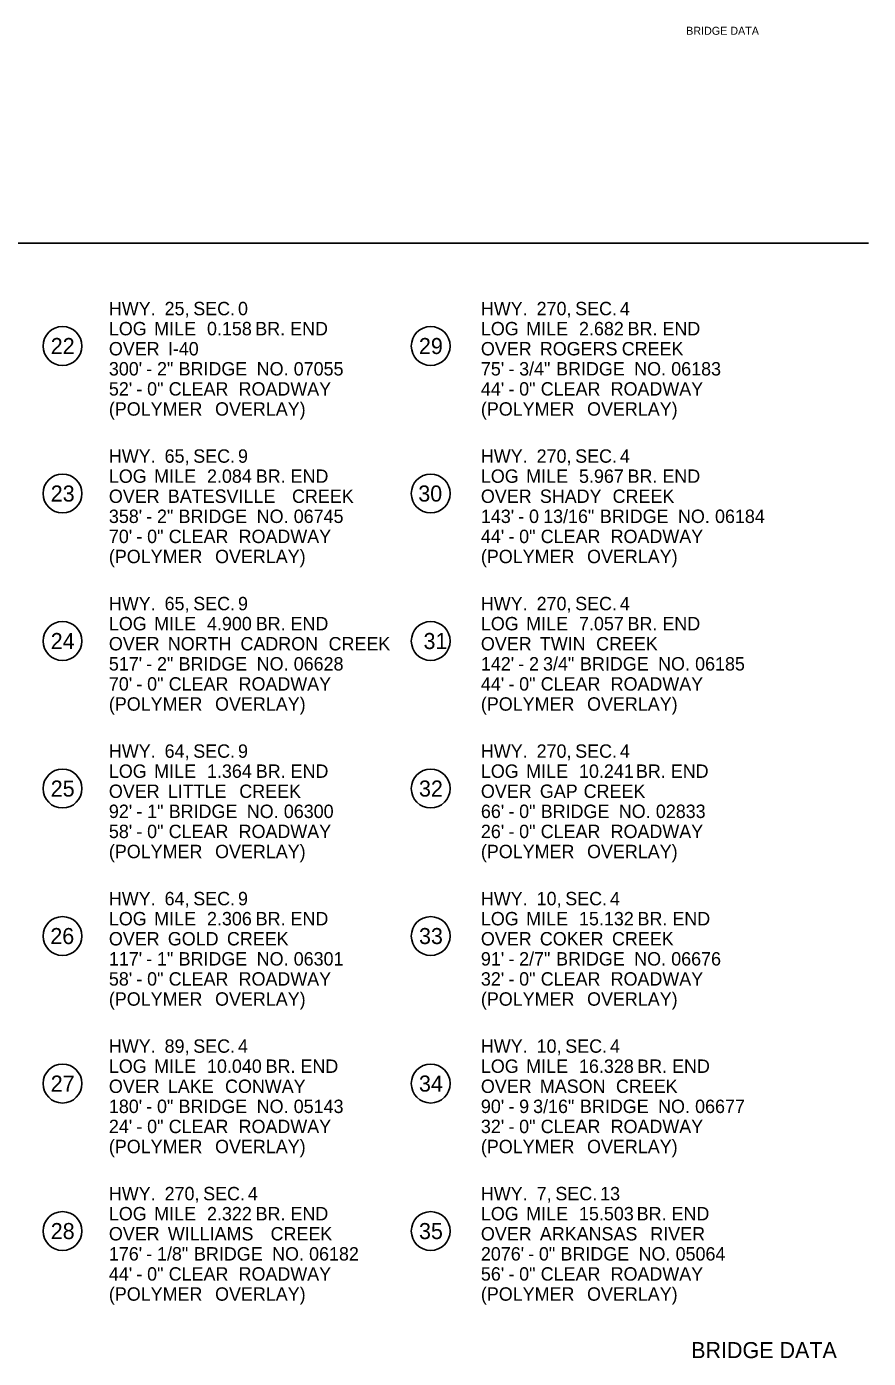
# Model space of a CAD drawing. Extents: x 1930546 to 1934225, y 596452 to 599553.
# Drawn here: x 1931513 to 1932142, y 598531 to 599525 of the extents above; entities that cross this region are included whole.
import ezdxf

# ---------------------------------------------------------------- set-up
doc = ezdxf.new("R2010")
doc.units = 0
for name, color, linetype in [('Default', 7, 'Continuous'), ('R_Border', 7, 'Continuous'), ('S_AREA_CALC', 7, 'Continuous')]:
    doc.layers.add(name, color=color, linetype=linetype)

msp = doc.modelspace()

# ---------------------------------------------------------------- linework, layer by layer
at = {"layer": 'R_Border'}
msp.add_line((1932141.6, 599363.54), (1930546.24, 599363.54), dxfattribs=at)
for centre in [(1931539.67, 599286.71), (1931814.72, 599286.71), (1931539.67, 599176.53), (1931814.72, 599176.53), (1931539.67, 599066.36), (1931814.72, 599066.36), (1931539.67, 598956.18), (1931814.72, 598956.18), (1931539.67, 598846.01), (1931814.72, 598846.01), (1931539.67, 598735.83), (1931814.72, 598735.83), (1931539.67, 598625.66), (1931814.72, 598625.66)]:
    msp.add_circle(centre, 14.52, dxfattribs=at)

# ---------------------------------------------------------------- texts
at = {"layer": 'Default'}
for s, p in [('HWY.', (1931574.31, 599309.69)), (' 25,', (1931612.22, 599309.69)), (' SEC.', (1931633.62, 599309.69)), (' 0', (1931667.03, 599309.69)), ('HWY.', (1931852.18, 599309.69)), (' 270,', (1931890.09, 599309.69)), (' SEC.', (1931918.89, 599309.69)), (' 4', (1931952.3, 599309.69)), ('LOG', (1931574.31, 599294.69)), (' MILE', (1931604.44, 599294.69)), (' 0.158', (1931643.88, 599294.69)), (' BR.', (1931679.96, 599294.69)), (' END', (1931706, 599294.69)), ('LOG', (1931852.18, 599294.69)), (' MILE', (1931882.31, 599294.69)), (' 2.682', (1931921.75, 599294.69)), (' BR.', (1931958.07, 599294.69)), (' END', (1931984.1, 599294.69)), ('OVER', (1931574.31, 599279.69)), (' I-40', (1931614.64, 599279.69)), ('OVER', (1931852.18, 599279.69)), (' ROGERS', (1931892.51, 599279.69)), (' CREEK', (1931953.68, 599279.69)), ("300'", (1931574.31, 599264.69)), (' 2"', (1931606.54, 599264.69)), (' BRIDGE', (1931622.67, 599264.69)), (' NO.', (1931680.99, 599264.69)), (' 07055', (1931708.65, 599264.69)), ("75'", (1931852.18, 599264.69)), (' 3/4"', (1931877.03, 599264.69)), (' BRIDGE', (1931904.65, 599264.69)), (' NO.', (1931962.97, 599264.69)), (' 06183', (1931990.63, 599264.69)), (' -', (1931598.51, 599264.69)), (' -', (1931869, 599264.69)), ("52'", (1931574.31, 599249.69)), (' -', (1931591.12, 599249.69)), (' 0"', (1931599.15, 599249.69)), (' CLEAR', (1931615.28, 599249.69)), (' ROADWAY', (1931667.5, 599249.69)), ("44'", (1931852.18, 599249.69)), (' -', (1931869, 599249.69)), (' 0"', (1931877.03, 599249.69)), (' CLEAR', (1931893.16, 599249.69)), (' ROADWAY', (1931945.38, 599249.69)), ('(POLYMER', (1931574.31, 599234.69)), (' OVERLAY)', (1931649.92, 599234.69)), ('(POLYMER', (1931852.18, 599234.69)), (' OVERLAY)', (1931927.79, 599234.69)), ('HWY.', (1931574.31, 599199.52)), (' 65,', (1931612.22, 599199.52)), (' SEC.', (1931633.62, 599199.52)), (' 9', (1931667.03, 599199.52)), ('HWY.', (1931852.18, 599199.52)), (' 270,', (1931890.09, 599199.52)), (' SEC.', (1931918.89, 599199.52)), (' 4', (1931952.3, 599199.52)), ('LOG', (1931574.31, 599184.52)), (' MILE', (1931604.44, 599184.52)), (' 2.084', (1931643.88, 599184.52)), (' BR.', (1931680.3, 599184.52)), (' END', (1931706.33, 599184.52)), ('LOG', (1931852.18, 599184.52)), (' MILE', (1931882.31, 599184.52)), (' 5.967', (1931921.75, 599184.52)), (' BR.', (1931958.02, 599184.52)), (' END', (1931984.05, 599184.52)), ('OVER', (1931574.31, 599169.52)), (' BATESVILLE', (1931614.64, 599169.52)), (' CREEK', (1931707.39, 599169.52)), ('OVER', (1931852.18, 599169.52)), (' SHADY', (1931892.51, 599169.52)), (' CREEK', (1931946.86, 599169.52)), ("358'", (1931574.31, 599154.52)), (' 2"', (1931606.54, 599154.52)), (' BRIDGE', (1931622.67, 599154.52)), (' NO.', (1931680.99, 599154.52)), (' 06745', (1931708.65, 599154.52)), ("143'", (1931852.18, 599154.52)), (' 0', (1931884.41, 599154.52)), (' 13/16"', (1931894.96, 599154.52)), (' BRIDGE', (1931937.37, 599154.52)), (' NO.', (1931995.68, 599154.52)), (' 06184', (1932023.34, 599154.52)), (' -', (1931598.51, 599154.52)), (' -', (1931876.39, 599154.52)), ("70'", (1931574.31, 599139.52)), (' -', (1931591.12, 599139.52)), (' 0"', (1931599.15, 599139.52)), (' CLEAR', (1931615.28, 599139.52)), (' ROADWAY', (1931667.5, 599139.52)), ("44'", (1931852.18, 599139.52)), (' -', (1931869, 599139.52)), (' 0"', (1931877.03, 599139.52)), (' CLEAR', (1931893.16, 599139.52)), (' ROADWAY', (1931945.38, 599139.52)), ('(POLYMER', (1931574.31, 599124.52)), (' OVERLAY)', (1931649.92, 599124.52)), ('(POLYMER', (1931852.18, 599124.52)), (' OVERLAY)', (1931927.79, 599124.52)), ('HWY.', (1931574.31, 599089.34)), (' 65,', (1931612.22, 599089.34)), (' SEC.', (1931633.62, 599089.34)), (' 9', (1931667.03, 599089.34)), ('HWY.', (1931852.18, 599089.34)), (' 270,', (1931890.09, 599089.34)), (' SEC.', (1931918.89, 599089.34)), (' 4', (1931952.3, 599089.34)), ('LOG', (1931574.31, 599074.34)), (' MILE', (1931604.44, 599074.34)), (' 4.900', (1931643.88, 599074.34)), (' BR.', (1931680.28, 599074.34)), (' END', (1931706.31, 599074.34)), ('LOG', (1931852.18, 599074.34)), (' MILE', (1931882.31, 599074.34)), (' 7.057', (1931921.75, 599074.34)), (' BR.', (1931958.02, 599074.34)), (' END', (1931984.05, 599074.34)), ('OVER', (1931574.31, 599059.34)), (' NORTH', (1931614.64, 599059.34)), (' CADRON', (1931668.88, 599059.34)), (' CREEK', (1931734.7, 599059.34)), ('OVER', (1931852.18, 599059.34)), (' TWIN', (1931892.51, 599059.34)), (' CREEK', (1931934.53, 599059.34)), ("517'", (1931574.31, 599044.34)), (' 2"', (1931606.54, 599044.34)), (' BRIDGE', (1931622.67, 599044.34)), (' NO.', (1931680.99, 599044.34)), (' 06628', (1931708.65, 599044.34)), ("142'", (1931852.18, 599044.34)), (' 2', (1931884.41, 599044.34)), (' 3/4"', (1931894.88, 599044.34)), (' BRIDGE', (1931922.5, 599044.34)), (' NO.', (1931980.82, 599044.34)), (' 06185', (1932008.48, 599044.34)), (' -', (1931598.51, 599044.34)), (' -', (1931876.39, 599044.34)), ("70'", (1931574.31, 599029.34)), (' 0"', (1931599.15, 599029.34)), (' CLEAR', (1931615.28, 599029.34)), (' ROADWAY', (1931667.5, 599029.34)), ("44'", (1931852.18, 599029.34)), (' 0"', (1931877.03, 599029.34)), (' CLEAR', (1931893.16, 599029.34)), (' ROADWAY', (1931945.38, 599029.34)), ('(POLYMER', (1931574.31, 599014.34)), (' -', (1931591.12, 599029.34)), (' OVERLAY)', (1931649.92, 599014.34)), ('(POLYMER', (1931852.18, 599014.34)), (' -', (1931869, 599029.34)), (' OVERLAY)', (1931927.79, 599014.34)), ('HWY.', (1931574.31, 598979.17)), (' 64,', (1931612.22, 598979.17)), (' SEC.', (1931633.62, 598979.17)), (' 9', (1931667.03, 598979.17)), ('HWY.', (1931852.18, 598979.17)), (' 270,', (1931890.09, 598979.17)), (' SEC.', (1931918.89, 598979.17)), (' 4', (1931952.3, 598979.17)), ('LOG', (1931574.31, 598964.17)), (' MILE', (1931604.44, 598964.17)), (' 1.364', (1931643.88, 598964.17)), (' BR.', (1931680.3, 598964.17)), (' END', (1931706.33, 598964.17)), ('LOG', (1931852.18, 598964.17)), (' MILE', (1931882.31, 598964.17)), (' 10.241', (1931921.75, 598964.17)), (' BR.', (1931964.26, 598964.17)), (' END', (1931990.29, 598964.17)), ('OVER', (1931574.31, 598949.17)), (' LITTLE', (1931614.64, 598949.17)), (' CREEK', (1931668, 598949.17)), ('OVER', (1931852.18, 598949.17)), (' GAP', (1931892.51, 598949.17)), (' CREEK', (1931925.22, 598949.17)), ("92'", (1931574.31, 598934.17)), (' -', (1931591.12, 598934.17)), (' 1"', (1931599.15, 598934.17)), (' BRIDGE', (1931615.28, 598934.17)), (' NO.', (1931673.6, 598934.17)), (' 06300', (1931701.26, 598934.17)), ("66'", (1931852.18, 598934.17)), (' -', (1931869, 598934.17)), (' 0"', (1931877.03, 598934.17)), (' BRIDGE', (1931893.16, 598934.17)), (' NO.', (1931951.47, 598934.17)), (' 02833', (1931979.13, 598934.17)), ("58'", (1931574.31, 598919.17)), (' 0"', (1931599.15, 598919.17)), (' CLEAR', (1931615.28, 598919.17)), (' ROADWAY', (1931667.5, 598919.17)), ("26'", (1931852.18, 598919.17)), (' 0"', (1931877.03, 598919.17)), (' CLEAR', (1931893.16, 598919.17)), (' ROADWAY', (1931945.38, 598919.17)), (' -', (1931591.12, 598919.17)), (' -', (1931869, 598919.17)), ('(POLYMER', (1931574.31, 598904.17)), (' OVERLAY)', (1931649.92, 598904.17)), ('(POLYMER', (1931852.18, 598904.17)), (' OVERLAY)', (1931927.79, 598904.17)), ('HWY.', (1931574.31, 598868.99)), (' 64,', (1931612.22, 598868.99)), (' SEC.', (1931633.62, 598868.99)), (' 9', (1931667.03, 598868.99)), ('HWY.', (1931852.18, 598868.99)), (' 10,', (1931890.09, 598868.99)), (' SEC.', (1931911.5, 598868.99)), (' 4', (1931944.91, 598868.99)), ('LOG', (1931574.31, 598853.99)), (' MILE', (1931604.44, 598853.99)), (' 2.306', (1931643.88, 598853.99)), (' BR.', (1931680.24, 598853.99)), (' END', (1931706.27, 598853.99)), ('LOG', (1931852.18, 598853.99)), (' MILE', (1931882.31, 598853.99)), (' 15.132', (1931921.75, 598853.99)), (' BR.', (1931965.46, 598853.99)), (' END', (1931991.49, 598853.99)), ('OVER', (1931574.31, 598838.99)), (' GOLD', (1931614.64, 598838.99)), (' CREEK', (1931658.77, 598838.99)), ('OVER', (1931852.18, 598838.99)), (' COKER', (1931892.51, 598838.99)), (' CREEK', (1931946.38, 598838.99)), ("117'", (1931574.31, 598823.99)), (' -', (1931598.51, 598823.99)), (' 1"', (1931606.54, 598823.99)), (' BRIDGE', (1931622.67, 598823.99)), (' NO.', (1931680.99, 598823.99)), (' 06301', (1931708.65, 598823.99)), ("91'", (1931852.18, 598823.99)), (' -', (1931869, 598823.99)), (' 2/7"', (1931877.03, 598823.99)), (' BRIDGE', (1931904.65, 598823.99)), (' NO.', (1931962.97, 598823.99)), (' 06676', (1931990.63, 598823.99)), ("58'", (1931574.31, 598808.99)), (' 0"', (1931599.15, 598808.99)), (' CLEAR', (1931615.28, 598808.99)), (' ROADWAY', (1931667.5, 598808.99)), ("32'", (1931852.18, 598808.99)), (' 0"', (1931877.03, 598808.99)), (' CLEAR', (1931893.16, 598808.99)), (' ROADWAY', (1931945.38, 598808.99)), (' -', (1931591.12, 598808.99)), (' -', (1931869, 598808.99)), ('(POLYMER', (1931574.31, 598793.99)), (' OVERLAY)', (1931649.92, 598793.99)), ('(POLYMER', (1931852.18, 598793.99)), (' OVERLAY)', (1931927.79, 598793.99)), ('HWY.', (1931574.31, 598758.82)), (' 89,', (1931612.22, 598758.82)), (' SEC.', (1931633.62, 598758.82)), (' 4', (1931667.03, 598758.82)), ('HWY.', (1931852.18, 598758.82)), (' 10,', (1931890.09, 598758.82)), (' SEC.', (1931911.5, 598758.82)), (' 4', (1931944.91, 598758.82)), ('LOG', (1931574.31, 598743.82)), (' MILE', (1931604.44, 598743.82)), (' 10.040', (1931643.88, 598743.82)), (' BR.', (1931687.67, 598743.82)), (' END', (1931713.7, 598743.82)), ('LOG', (1931852.18, 598743.82)), (' MILE', (1931882.31, 598743.82)), (' 16.328', (1931921.75, 598743.82)), (' BR.', (1931965.23, 598743.82)), (' END', (1931991.26, 598743.82)), ('OVER', (1931574.31, 598728.82)), (' LAKE', (1931614.64, 598728.82)), (' CONWAY', (1931657.35, 598728.82)), ('OVER', (1931852.18, 598728.82)), (' MASON', (1931892.51, 598728.82)), (' CREEK', (1931949.32, 598728.82)), ("180'", (1931574.31, 598713.82)), (' -', (1931598.51, 598713.82)), (' 0"', (1931606.54, 598713.82)), (' BRIDGE', (1931622.67, 598713.82)), (' NO.', (1931680.99, 598713.82)), (' 05143', (1931708.65, 598713.82)), ("90'", (1931852.18, 598713.82)), (' -', (1931869, 598713.82)), (' 9', (1931877.03, 598713.82)), (' 3/16"', (1931887.47, 598713.82)), (' BRIDGE', (1931922.49, 598713.82)), (' NO.', (1931980.8, 598713.82)), (' 06677', (1932008.46, 598713.82)), ("24'", (1931574.31, 598698.82)), (' 0"', (1931599.15, 598698.82)), (' CLEAR', (1931615.28, 598698.82)), (' ROADWAY', (1931667.5, 598698.82)), ("32'", (1931852.18, 598698.82)), (' 0"', (1931877.03, 598698.82)), (' CLEAR', (1931893.16, 598698.82)), (' ROADWAY', (1931945.38, 598698.82)), (' -', (1931591.12, 598698.82)), (' -', (1931869, 598698.82)), ('(POLYMER', (1931574.31, 598683.82)), (' OVERLAY)', (1931649.92, 598683.82)), ('(POLYMER', (1931852.18, 598683.82)), (' OVERLAY)', (1931927.79, 598683.82)), ('HWY.', (1931574.31, 598648.64)), (' 270,', (1931612.22, 598648.64)), (' SEC.', (1931641.01, 598648.64)), (' 4', (1931674.42, 598648.64)), ('HWY.', (1931852.18, 598648.64)), (' 7,', (1931890.09, 598648.64)), (' SEC.', (1931904.11, 598648.64)), (' 13', (1931937.52, 598648.64)), ('LOG', (1931574.31, 598633.64)), (' MILE', (1931604.44, 598633.64)), (' 2.322', (1931643.88, 598633.64)), (' BR.', (1931680.2, 598633.64)), (' END', (1931706.23, 598633.64)), ('LOG', (1931852.18, 598633.64)), (' MILE', (1931882.31, 598633.64)), (' 15.503', (1931921.75, 598633.64)), (' BR.', (1931964.84, 598633.64)), (' END', (1931990.88, 598633.64)), ('OVER', (1931574.31, 598618.64)), (' WILLIAMS', (1931614.64, 598618.64)), (' CREEK', (1931691.37, 598618.64)), ('OVER', (1931852.18, 598618.64)), (' ARKANSAS', (1931892.51, 598618.64)), (' RIVER', (1931975.01, 598618.64)), ("176'", (1931574.31, 598603.64)), (' -', (1931598.51, 598603.64)), (' 1/8"', (1931606.54, 598603.64)), (' BRIDGE', (1931634.17, 598603.64)), (' NO.', (1931692.48, 598603.64)), (' 06182', (1931720.14, 598603.64)), ("2076'", (1931852.18, 598603.64)), (' -', (1931883.77, 598603.64)), (' 0"', (1931891.8, 598603.64)), (' BRIDGE', (1931907.94, 598603.64)), (' NO.', (1931966.25, 598603.64)), (' 05064', (1931993.91, 598603.64)), ("44'", (1931574.31, 598588.64)), (' 0"', (1931599.15, 598588.64)), (' CLEAR', (1931615.28, 598588.64)), (' ROADWAY', (1931667.5, 598588.64)), ("56'", (1931852.18, 598588.64)), (' 0"', (1931877.03, 598588.64)), (' CLEAR', (1931893.16, 598588.64)), (' ROADWAY', (1931945.38, 598588.64)), (' -', (1931591.12, 598588.64)), (' -', (1931869, 598588.64)), ('(POLYMER', (1931574.31, 598573.64)), (' OVERLAY)', (1931649.92, 598573.64)), ('(POLYMER', (1931852.18, 598573.64)), (' OVERLAY)', (1931927.79, 598573.64))]:
    msp.add_text(s, height=10, dxfattribs=at).set_placement(p)
at = {"layer": 'R_Border'}
for s, p in [('22', (1931530.88, 599280.71)), ('29', (1931805.88, 599280.71)), ('23', (1931530.88, 599170.53)), ('30', (1931805.41, 599170.53)), ('24', (1931530.88, 599060.36)), ('31', (1931809.33, 599060.36)), ('25', (1931530.88, 598950.18)), ('32', (1931805.93, 598950.18)), ('26', (1931530.55, 598840.01)), ('33', (1931805.93, 598840.01)), ('27', (1931530.88, 598729.83)), ('34', (1931805.93, 598729.83)), ('28', (1931530.88, 598619.66)), ('35', (1931805.93, 598619.66)), ('BRIDGE DATA', (1932009.26, 598530.75))]:
    msp.add_text(s, height=12, rotation=360, dxfattribs=at).set_placement(p)
at = {"layer": 'S_AREA_CALC'}
msp.add_text('BRIDGE DATA', height=6, rotation=360, dxfattribs=at).set_placement((1932005.48, 599519.17))

doc.saveas('drawing.dxf')
